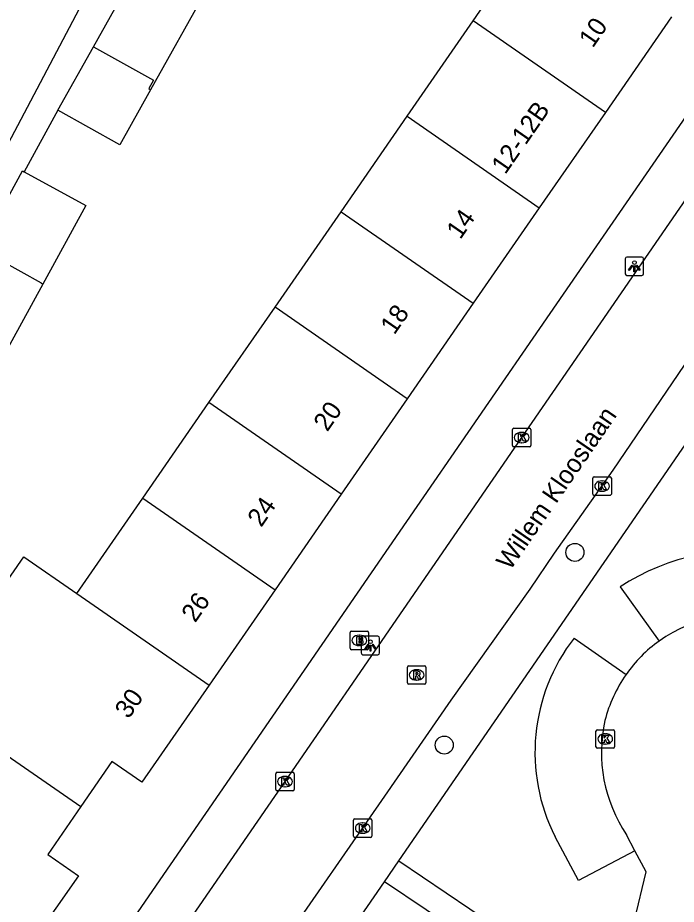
# Model space of a CAD drawing. Extents: x 160356 to 161355, y 381727 to 382845.
# Drawn here: x 160835.39 to 160871.04, y 382011.19 to 382059.16 of the extents above; entities that cross this region are included whole.
import ezdxf

# ---------------------------------------------------------------- set-up
doc = ezdxf.new("R2010")
doc.units = 0
for name, color, linetype in [('IMGEO_Boom', 7, 'Continuous'), ('IMGEO_Brandkraan', 7, 'Continuous'), ('IMGEO_Kolk', 7, 'Continuous'), ('IMGEO_Lichtpunt', 7, 'Continuous'), ('IMGEO_Openbare_ruimte_label', 7, 'Continuous'), ('IMGEO_Pand', 7, 'Continuous'), ('IMGEO_Pand_nummerreeks', 7, 'Continuous'), ('IMGEO_Parkeervlak_open', 7, 'Continuous'), ('IMGEO_Rijbaan_lokaal_open', 7, 'Continuous'), ('IMGEO_Rioolput', 7, 'Continuous'), ('IMGEO_Voetpad_open', 7, 'Continuous')]:
    doc.layers.add(name, color=color, linetype=linetype)

msp = doc.modelspace()

# ---------------------------------------------------------------- linework, layer by layer
at = {"layer": 'IMGEO_Boom'}
for centre in [(160865.548, 382030.233), (160858.476, 382019.805)]:
    msp.add_circle(centre, 0.489, dxfattribs=at)
at = {"layer": 'IMGEO_Brandkraan'}
for p, q in [((160853.375, 382025.042), (160853.375, 382025.894)), ((160853.45, 382025.968), (160854.302, 382025.968)), ((160854.376, 382025.894), (160854.376, 382025.042)), ((160853.863, 382025.748), (160853.888, 382025.748)), ((160854.302, 382024.968), (160853.45, 382024.968)), ((160853.886, 382025.188), (160853.861, 382025.188))]:
    msp.add_line(p, q, dxfattribs=at)
for points in [[(160853.375, 382025.042), (160853.375, 382025.894)], [(160853.45, 382025.968), (160854.302, 382025.968)], [(160854.376, 382025.894), (160854.376, 382025.042)], [(160853.723, 382025.668), (160853.723, 382025.268), (160853.936, 382025.268)], [(160853.954, 382025.668), (160853.723, 382025.668)], [(160853.902, 382025.587), (160853.848, 382025.587), (160853.848, 382025.511)], [(160853.848, 382025.511), (160853.901, 382025.511)], [(160853.91, 382025.435), (160853.848, 382025.435), (160853.848, 382025.354)], [(160854.302, 382024.968), (160853.45, 382024.968)], [(160853.848, 382025.354), (160853.91, 382025.354)]]:
    msp.add_lwpolyline(points, dxfattribs=at)
for centre, radius, start, end in [((160853.452, 382025.892), 0.0765, 91.552, 178.448), ((160853.452, 382025.892), 0.0765, 91.552, 178.448), ((160854.3, 382025.892), 0.0765, 1.552, 88.448), ((160854.3, 382025.892), 0.0765, 1.552, 88.448), ((160853.903, 382025.549), 0.0379, 267.8285, 90.9355), ((160853.911, 382025.394), 0.0404, 269.8759, 90.5077), ((160853.958, 382025.523), 0.145, 59.4692, 91.5367), ((160853.983, 382025.57), 0.0922, 285.5137, 58.1501), ((160853.988, 382025.378), 0.105, 301.3115, 78.989), ((160853.452, 382025.044), 0.0765, 181.552, 268.448), ((160853.452, 382025.044), 0.0765, 181.552, 268.448), ((160853.942, 382025.519), 0.251, 268.6676, 293.5347), ((160854.3, 382025.044), 0.0765, 271.552, 358.448), ((160854.3, 382025.044), 0.0765, 271.552, 358.448)]:
    msp.add_arc(centre, radius, start, end, dxfattribs=at)
for centre, major_axis, ratio, start_param, end_param in [((160853.862, 382025.468), (-0.387, 0.002), 0.722429, 4.712389, 7.853982), ((160853.887, 382025.468), (-0.39, 0.002), 0.717154, 1.570796, 4.712389)]:
    msp.add_ellipse(centre, major_axis=major_axis, ratio=ratio, start_param=start_param, end_param=end_param, dxfattribs=at)
at = {"layer": 'IMGEO_Kolk'}
for p, q in [((160862.167, 382036.022), (160862.167, 382036.874)), ((160862.242, 382036.948), (160863.094, 382036.948)), ((160863.168, 382036.874), (160863.168, 382036.022)), ((160862.655, 382036.728), (160862.68, 382036.728)), ((160863.094, 382035.948), (160862.242, 382035.948)), ((160862.678, 382036.168), (160862.653, 382036.168)), ((160866.524, 382033.391), (160866.524, 382034.243)), ((160866.599, 382034.317), (160867.451, 382034.317)), ((160867.012, 382034.097), (160867.037, 382034.097)), ((160867.525, 382034.243), (160867.525, 382033.391)), ((160867.035, 382033.537), (160867.01, 382033.537)), ((160867.451, 382033.317), (160866.599, 382033.317)), ((160866.691, 382019.71), (160866.691, 382020.562)), ((160866.766, 382020.636), (160867.618, 382020.636)), ((160867.692, 382020.562), (160867.692, 382019.71)), ((160867.179, 382020.416), (160867.204, 382020.416)), ((160867.618, 382019.636), (160866.766, 382019.636)), ((160867.202, 382019.856), (160867.177, 382019.856)), ((160849.357, 382017.406), (160849.357, 382018.258)), ((160849.432, 382018.332), (160850.284, 382018.332)), ((160850.358, 382018.258), (160850.358, 382017.406)), ((160849.845, 382018.112), (160849.87, 382018.112)), ((160850.284, 382017.332), (160849.432, 382017.332)), ((160849.868, 382017.552), (160849.843, 382017.552)), ((160853.639, 382015.811), (160854.491, 382015.811)), ((160853.564, 382014.885), (160853.564, 382015.737)), ((160854.052, 382015.591), (160854.077, 382015.591)), ((160854.565, 382015.737), (160854.565, 382014.885)), ((160854.491, 382014.811), (160853.639, 382014.811)), ((160854.075, 382015.031), (160854.05, 382015.031))]:
    msp.add_line(p, q, dxfattribs=at)
for points in [[(160862.167, 382036.022), (160862.167, 382036.874)], [(160862.242, 382036.948), (160863.094, 382036.948)], [(160863.168, 382036.874), (160863.168, 382036.022)], [(160862.488, 382036.648), (160862.611, 382036.648), (160862.611, 382036.497), (160862.741, 382036.648), (160862.905, 382036.648), (160862.759, 382036.497), (160862.912, 382036.248), (160862.76, 382036.248), (160862.675, 382036.412), (160862.611, 382036.345), (160862.611, 382036.248), (160862.488, 382036.248), (160862.488, 382036.648)], [(160863.094, 382035.948), (160862.242, 382035.948)], [(160866.524, 382033.391), (160866.524, 382034.243)], [(160866.599, 382034.317), (160867.451, 382034.317)], [(160866.845, 382034.017), (160866.968, 382034.017), (160866.968, 382033.866), (160867.098, 382034.017), (160867.262, 382034.017), (160867.116, 382033.866), (160867.269, 382033.617), (160867.117, 382033.617), (160867.032, 382033.781), (160866.968, 382033.714), (160866.968, 382033.617), (160866.845, 382033.617), (160866.845, 382034.017)], [(160867.525, 382034.243), (160867.525, 382033.391)], [(160867.451, 382033.317), (160866.599, 382033.317)], [(160866.691, 382019.71), (160866.691, 382020.562)], [(160866.766, 382020.636), (160867.618, 382020.636)], [(160867.692, 382020.562), (160867.692, 382019.71)], [(160867.012, 382020.336), (160867.135, 382020.336), (160867.135, 382020.185), (160867.265, 382020.336), (160867.429, 382020.336), (160867.283, 382020.185), (160867.436, 382019.936), (160867.284, 382019.936), (160867.199, 382020.1), (160867.135, 382020.033), (160867.135, 382019.936), (160867.012, 382019.936), (160867.012, 382020.336)], [(160867.618, 382019.636), (160866.766, 382019.636)], [(160849.357, 382017.406), (160849.357, 382018.258)], [(160849.432, 382018.332), (160850.284, 382018.332)], [(160850.358, 382018.258), (160850.358, 382017.406)], [(160849.678, 382018.032), (160849.801, 382018.032), (160849.801, 382017.881), (160849.931, 382018.032), (160850.095, 382018.032), (160849.949, 382017.881), (160850.102, 382017.632), (160849.95, 382017.632), (160849.865, 382017.796), (160849.801, 382017.729), (160849.801, 382017.632), (160849.678, 382017.632), (160849.678, 382018.032)], [(160850.284, 382017.332), (160849.432, 382017.332)], [(160853.639, 382015.811), (160854.491, 382015.811)], [(160853.564, 382014.885), (160853.564, 382015.737)], [(160853.885, 382015.511), (160854.008, 382015.511), (160854.008, 382015.36), (160854.138, 382015.511), (160854.302, 382015.511), (160854.156, 382015.36), (160854.309, 382015.111), (160854.157, 382015.111), (160854.072, 382015.275), (160854.008, 382015.208), (160854.008, 382015.111), (160853.885, 382015.111), (160853.885, 382015.511)], [(160854.565, 382015.737), (160854.565, 382014.885)], [(160854.491, 382014.811), (160853.639, 382014.811)]]:
    msp.add_lwpolyline(points, dxfattribs=at)
for centre, start, end in [((160862.244, 382036.872), 91.552, 178.448), ((160862.244, 382036.872), 91.552, 178.448), ((160863.092, 382036.872), 1.552, 88.448), ((160863.092, 382036.872), 1.552, 88.448), ((160862.244, 382036.024), 181.552, 268.448), ((160862.244, 382036.024), 181.552, 268.448), ((160863.092, 382036.024), 271.552, 358.448), ((160863.092, 382036.024), 271.552, 358.448), ((160866.601, 382034.241), 91.552, 178.448), ((160866.601, 382034.241), 91.552, 178.448), ((160867.449, 382034.241), 1.552, 88.448), ((160867.449, 382034.241), 1.552, 88.448), ((160866.601, 382033.393), 181.552, 268.448), ((160866.601, 382033.393), 181.552, 268.448), ((160867.449, 382033.393), 271.552, 358.448), ((160867.449, 382033.393), 271.552, 358.448), ((160866.768, 382020.56), 91.552, 178.448), ((160866.768, 382020.56), 91.552, 178.448), ((160867.616, 382020.56), 1.552, 88.448), ((160867.616, 382020.56), 1.552, 88.448), ((160866.768, 382019.712), 181.552, 268.448), ((160866.768, 382019.712), 181.552, 268.448), ((160867.616, 382019.712), 271.552, 358.448), ((160867.616, 382019.712), 271.552, 358.448), ((160849.434, 382018.256), 91.552, 178.448), ((160849.434, 382018.256), 91.552, 178.448), ((160850.282, 382018.256), 1.552, 88.448), ((160850.282, 382018.256), 1.552, 88.448), ((160849.434, 382017.408), 181.552, 268.448), ((160849.434, 382017.408), 181.552, 268.448), ((160850.282, 382017.408), 271.552, 358.448), ((160850.282, 382017.408), 271.552, 358.448), ((160853.641, 382015.735), 91.552, 178.448), ((160853.641, 382015.735), 91.552, 178.448), ((160854.489, 382015.735), 1.552, 88.448), ((160854.489, 382015.735), 1.552, 88.448), ((160853.641, 382014.887), 181.552, 268.448), ((160853.641, 382014.887), 181.552, 268.448), ((160854.489, 382014.887), 271.552, 358.448), ((160854.489, 382014.887), 271.552, 358.448)]:
    msp.add_arc(centre, 0.0765, start, end, dxfattribs=at)
for centre, major_axis, ratio, start_param, end_param in [((160862.654, 382036.448), (-0.387, 0.002), 0.722429, 4.712389, 7.853982), ((160862.679, 382036.448), (-0.39, 0.002), 0.717154, 1.570796, 4.712389), ((160867.011, 382033.817), (-0.387, 0.002), 0.722429, 4.712389, 7.853982), ((160867.036, 382033.817), (-0.39, 0.002), 0.717154, 1.570796, 4.712389), ((160867.178, 382020.136), (-0.387, 0.002), 0.722429, 4.712389, 7.853982), ((160867.203, 382020.136), (-0.39, 0.002), 0.717154, 1.570796, 4.712389), ((160849.844, 382017.832), (-0.387, 0.002), 0.722429, 4.712389, 7.853982), ((160849.869, 382017.832), (-0.39, 0.002), 0.717154, 1.570796, 4.712389), ((160854.051, 382015.311), (-0.387, 0.002), 0.722429, 4.712389, 7.853982), ((160854.076, 382015.311), (-0.39, 0.002), 0.717154, 1.570796, 4.712389)]:
    msp.add_ellipse(centre, major_axis=major_axis, ratio=ratio, start_param=start_param, end_param=end_param, dxfattribs=at)
at = {"layer": 'IMGEO_Lichtpunt'}
for p, q in [((160868.272, 382046.119), (160868.272, 382045.312)), ((160868.272, 382046.119), (160868.272, 382045.312)), ((160869.174, 382046.214), (160868.366, 382046.214)), ((160869.174, 382046.214), (160868.366, 382046.214)), ((160869.268, 382045.312), (160869.268, 382046.119)), ((160869.268, 382045.312), (160869.268, 382046.119)), ((160868.366, 382045.218), (160869.174, 382045.218)), ((160868.366, 382045.218), (160869.174, 382045.218)), ((160853.982, 382025.598), (160853.982, 382024.791)), ((160853.982, 382025.598), (160853.982, 382024.791)), ((160854.884, 382025.693), (160854.076, 382025.693)), ((160854.884, 382025.693), (160854.076, 382025.693)), ((160854.978, 382024.791), (160854.978, 382025.598)), ((160854.978, 382024.791), (160854.978, 382025.598)), ((160854.076, 382024.697), (160854.884, 382024.697)), ((160854.076, 382024.697), (160854.884, 382024.697))]:
    msp.add_line(p, q, dxfattribs=at)
for points in [[(160868.646, 382045.783), (160868.685, 382045.755), (160868.497, 382045.493), (160868.459, 382045.52), (160868.646, 382045.783)], [(160868.748, 382045.735), (160868.795, 382045.735), (160868.795, 382045.413), (160868.748, 382045.413), (160868.748, 382045.735)], [(160868.858, 382045.755), (160868.896, 382045.782), (160869.083, 382045.52), (160869.044, 382045.492), (160868.858, 382045.755)], [(160854.356, 382025.262), (160854.395, 382025.234), (160854.207, 382024.972), (160854.169, 382024.999), (160854.356, 382025.262)], [(160854.458, 382025.214), (160854.505, 382025.214), (160854.505, 382024.892), (160854.458, 382024.892), (160854.458, 382025.214)], [(160854.568, 382025.234), (160854.606, 382025.261), (160854.793, 382024.999), (160854.754, 382024.971), (160854.568, 382025.234)]]:
    msp.add_lwpolyline(points, dxfattribs=at)
for centre in [(160868.771, 382045.917), (160854.481, 382025.396)]:
    msp.add_circle(centre, 0.0994, dxfattribs=at)
for centre, start, end in [((160868.366, 382046.119), 90, 180), ((160868.366, 382046.119), 90, 180), ((160869.174, 382046.119), 0, 90), ((160869.174, 382046.119), 0, 90), ((160868.366, 382045.312), 180, 270), ((160868.366, 382045.312), 180, 270), ((160869.174, 382045.312), 270, 0), ((160869.174, 382045.312), 270, 360), ((160854.076, 382025.598), 90, 180), ((160854.076, 382025.598), 90, 180), ((160854.884, 382025.598), 0, 90), ((160854.884, 382025.598), 0, 90), ((160854.076, 382024.791), 180, 270), ((160854.076, 382024.791), 180, 270), ((160854.884, 382024.791), 270, 0), ((160854.884, 382024.791), 270, 360)]:
    msp.add_arc(centre, 0.0946, start, end, dxfattribs=at)
at = {"layer": 'IMGEO_Pand'}
for points in [[(160860.043, 382058.997), (160860.598, 382059.799), (160858.504, 382061.331), (160861.506, 382065.666), (160863.619, 382064.162)], [(160839.481, 382057.598), (160842.243, 382062.537)], [(160842.243, 382062.537), (160845.594, 382060.663), (160842.578, 382055.268)], [(160856.467, 382053.832), (160860.043, 382058.997)], [(160867.2, 382054.044), (160860.043, 382058.997)], [(160870.774, 382059.209), (160867.2, 382054.044)], [(160837.557, 382054.157), (160839.481, 382057.598)], [(160839.481, 382057.598), (160842.734, 382055.794), (160842.478, 382055.332), (160842.578, 382055.268)], [(160842.578, 382055.268), (160840.909, 382052.283), (160837.557, 382054.157)], [(160852.891, 382048.667), (160856.467, 382053.832)], [(160856.467, 382053.832), (160863.624, 382048.878)], [(160867.2, 382054.044), (160863.624, 382048.878)], [(160833.334, 382046.658), (160835.643, 382050.875), (160835.733, 382050.826)], [(160835.733, 382050.826), (160839.066, 382049.001), (160836.741, 382044.754)], [(160863.624, 382048.878), (160860.049, 382043.712)], [(160849.315, 382043.503), (160852.891, 382048.667)], [(160852.891, 382048.667), (160860.049, 382043.712)], [(160833.334, 382046.658), (160836.646, 382044.821), (160836.741, 382044.754)], [(160836.741, 382044.754), (160834.423, 382040.52), (160831, 382042.394)], [(160860.049, 382043.712), (160856.475, 382038.547)], [(160845.739, 382038.337), (160849.315, 382043.503)], [(160856.475, 382038.547), (160849.315, 382043.503)], [(160842.163, 382033.173), (160845.739, 382038.337)], [(160852.9, 382033.381), (160845.739, 382038.337)], [(160856.475, 382038.547), (160852.9, 382033.381)], [(160838.587, 382028.008), (160842.163, 382033.173)], [(160842.163, 382033.173), (160849.324, 382028.215)], [(160852.9, 382033.381), (160849.324, 382028.215)], [(160830.439, 382022.245), (160832.077, 382024.737), (160835.717, 382029.994), (160838.587, 382028.008)], [(160838.587, 382028.008), (160845.75, 382023.05)], [(160849.324, 382028.215), (160845.75, 382023.05)], [(160845.75, 382023.05), (160842.113, 382017.795), (160840.488, 382018.919), (160838.803, 382016.475)], [(160830.439, 382022.245), (160830.746, 382022.033), (160838.803, 382016.475)], [(160838.803, 382016.475), (160837.021, 382013.892), (160838.679, 382012.731), (160835.001, 382007.479)]]:
    msp.add_lwpolyline(points, dxfattribs=at)
at = {"layer": 'IMGEO_Parkeervlak_open'}
for points in [[(160868.002, 382028.365), (160870.112, 382025.436)], [(160865.509, 382025.598), (160868.321, 382023.624)], [(160868.801, 382014.089), (160865.741, 382012.48), (160864.478, 382014.847)]]:
    msp.add_lwpolyline(points, dxfattribs=at)
for centre, radius, start, end in [((160874.552, 382018.402), 11.923, 79.041, 123.3238), ((160873.481, 382019.409), 10.092, 142.1731, 206.8713)]:
    msp.add_arc(centre, radius, start, end, dxfattribs=at)
at = {"layer": 'IMGEO_Rijbaan_lokaal_open'}
for points in [[(160900.454, 382091.336), (160898.732, 382088.827), (160897.579, 382087.17), (160888.911, 382074.534), (160875.487, 382055.069), (160862.667, 382036.458), (160849.849, 382017.829), (160838.733, 382001.705), (160827.599, 381985.555), (160816.487, 381969.406), (160806.996, 381955.65)], [(160811.585, 381953.706), (160812.427, 381954.838), (160843.491, 382000), (160849.506, 382008.744), (160855.258, 382017.034), (160858.854, 382022.23), (160863.124, 382028.242), (160864.448, 382030.182), (160867.631, 382034.676), (160871.484, 382040.355), (160873.174, 382042.828), (160877.127, 382048.557), (160882.027, 382055.784), (160885.092, 382060.107), (160889.498, 382066.61), (160894.202, 382073.493), (160902.442, 382085.568), (160903.558, 382087.228), (160905.012, 382089.324)]]:
    msp.add_lwpolyline(points, dxfattribs=at)
at = {"layer": 'IMGEO_Rioolput'}
for p, q in [((160856.484, 382023.173), (160856.484, 382024.025)), ((160856.559, 382024.099), (160857.411, 382024.099)), ((160857.485, 382024.025), (160857.485, 382023.173)), ((160856.972, 382023.879), (160856.997, 382023.879)), ((160857.411, 382023.099), (160856.559, 382023.099)), ((160856.995, 382023.319), (160856.97, 382023.319))]:
    msp.add_line(p, q, dxfattribs=at)
for points in [[(160856.484, 382023.173), (160856.484, 382024.025)], [(160856.559, 382024.099), (160857.411, 382024.099)], [(160857.485, 382024.025), (160857.485, 382023.173)], [(160857.073, 382023.797), (160856.821, 382023.799), (160856.821, 382023.399)], [(160856.821, 382023.399), (160856.945, 382023.399), (160856.945, 382023.561), (160856.956, 382023.561)], [(160856.999, 382023.718), (160856.945, 382023.718), (160856.945, 382023.637)], [(160856.945, 382023.637), (160856.997, 382023.637)], [(160857.003, 382023.532), (160857.074, 382023.399), (160857.214, 382023.399), (160857.149, 382023.525)], [(160857.411, 382023.099), (160856.559, 382023.099)]]:
    msp.add_lwpolyline(points, dxfattribs=at)
for centre, radius, start, end in [((160856.561, 382024.023), 0.0765, 91.552, 178.448), ((160856.561, 382024.023), 0.0765, 91.552, 178.448), ((160857.409, 382024.023), 0.0765, 1.552, 88.448), ((160857.409, 382024.023), 0.0765, 1.552, 88.448), ((160856.955, 382023.508), 0.0533, 26.0293, 88.6989), ((160856.981, 382023.826), 0.19, 274.7715, 282.9687), ((160857.005, 382023.622), 0.0964, 77.0061, 93.1865), ((160857.019, 382023.679), 0.0378, 276.6634, 79.6772), ((160857.072, 382023.687), 0.109, 350.3612, 89.416), ((160857.07, 382023.687), 0.112, 277.5842, 350.9817), ((160857.054, 382023.472), 0.108, 29.5134, 73.7905), ((160856.561, 382023.175), 0.0765, 181.552, 268.448), ((160856.561, 382023.175), 0.0765, 181.552, 268.448), ((160857.409, 382023.175), 0.0765, 271.552, 358.448), ((160857.409, 382023.175), 0.0765, 271.552, 358.448)]:
    msp.add_arc(centre, radius, start, end, dxfattribs=at)
for centre, major_axis, ratio, start_param, end_param in [((160856.971, 382023.599), (-0.387, 0.002), 0.722429, 4.712389, 7.853982), ((160856.996, 382023.599), (-0.39, 0.002), 0.717154, 1.570796, 4.712389)]:
    msp.add_ellipse(centre, major_axis=major_axis, ratio=ratio, start_param=start_param, end_param=end_param, dxfattribs=at)
at = {"layer": 'IMGEO_Voetpad_open'}
for points in [[(160834.328, 382051.343), (160847.298, 382075.927)], [(160804.86, 381957.022), (160809.509, 381963.746), (160815.556, 381972.499), (160830.024, 381993.552), (160843.658, 382013.325), (160856.447, 382031.904), (160864.216, 382043.168), (160877.531, 382062.485), (160882.102, 382069.151), (160883.88, 382071.73)], [(160837.557, 382054.157), (160835.733, 382050.826)], [(160856.025, 382013.549), (160879.4, 382047.514)], [(160868.801, 382014.089), (160868.345, 382014.956)], [(160856.025, 382013.549), (160862.42, 382009.21), (160864.718, 382006.576), (160868.779, 382010.311), (160869.404, 382012.942), (160868.801, 382014.089)], [(160855.241, 382012.41), (160856.025, 382013.549)], [(160850.803, 382005.961), (160855.241, 382012.41)], [(160850.803, 382005.961), (160854.038, 382004.118), (160859.749, 382009.38), (160855.241, 382012.41)]]:
    msp.add_lwpolyline(points, dxfattribs=at)
for centre, radius, start, end in [((160874.584, 382019.224), 7.654, 22.6353, 125.7522), ((160874.601, 382019.208), 7.678, 125.7831, 144.8848), ((160874.734, 382019.156), 7.816, 145.1356, 165.3258), ((160874.946, 382019.409), 7.963, 167.4748, 214.0018)]:
    msp.add_arc(centre, radius, start, end, dxfattribs=at)

# ---------------------------------------------------------------- texts
at = {"layer": 'IMGEO_Openbare_ruimte_label'}
msp.add_text('Willem Klooslaan', height=1, rotation=55.4679, dxfattribs=at).set_placement((160862.045, 382029.214))
at = {"layer": 'IMGEO_Pand_nummerreeks'}
for s, rotation, p in [('10', 55.3153, (160866.518, 382057.489)), ('12-12B', 55.3143, (160861.781, 382050.643)), ('14', 55.3143, (160859.346, 382047.124)), ('18', 55.3143, (160855.772, 382041.962)), ('20', 55.3143, (160852.147, 382036.721)), ('24', 55.3143, (160848.569, 382031.553)), ('26', 55.3143, (160844.995, 382026.388)), ('30', 55.3133, (160841.391, 382021.18))]:
    msp.add_text(s, height=1, rotation=rotation, dxfattribs=at).set_placement(p)

doc.saveas('drawing.dxf')
